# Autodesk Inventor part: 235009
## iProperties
Created: 2006-08
Part Number: 235009
Material: 8 vz
Description: Sechskantmutter
Vendor: Autodesk Inc.
Document SubType Name: Modeling
Standard: DIN 934
Designer: I.Baliuc
Standards Organization: DIN
Language: de-DE
Size Designation: M8
Categories: <MemberInstance Version="R10.0.0"><Categories><Category DisplayName="Schrauben" InternalName="e4da775c-781d-43d5-af7c-5136215cf5a6" Mnemonic="FSTN"><Category Di
Density: 7.85 g/cm^3
Abmessung: M8
Author: T.Messerschmitt
Comments: DIN 934 - M8
Revision Number: 235009
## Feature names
1. Körper [Extrusion]
2. Fase1 [Revolution]
3. Gewinde [Hole]
4. Fase2 [Chamfer]
5. Fase3 [Chamfer]
